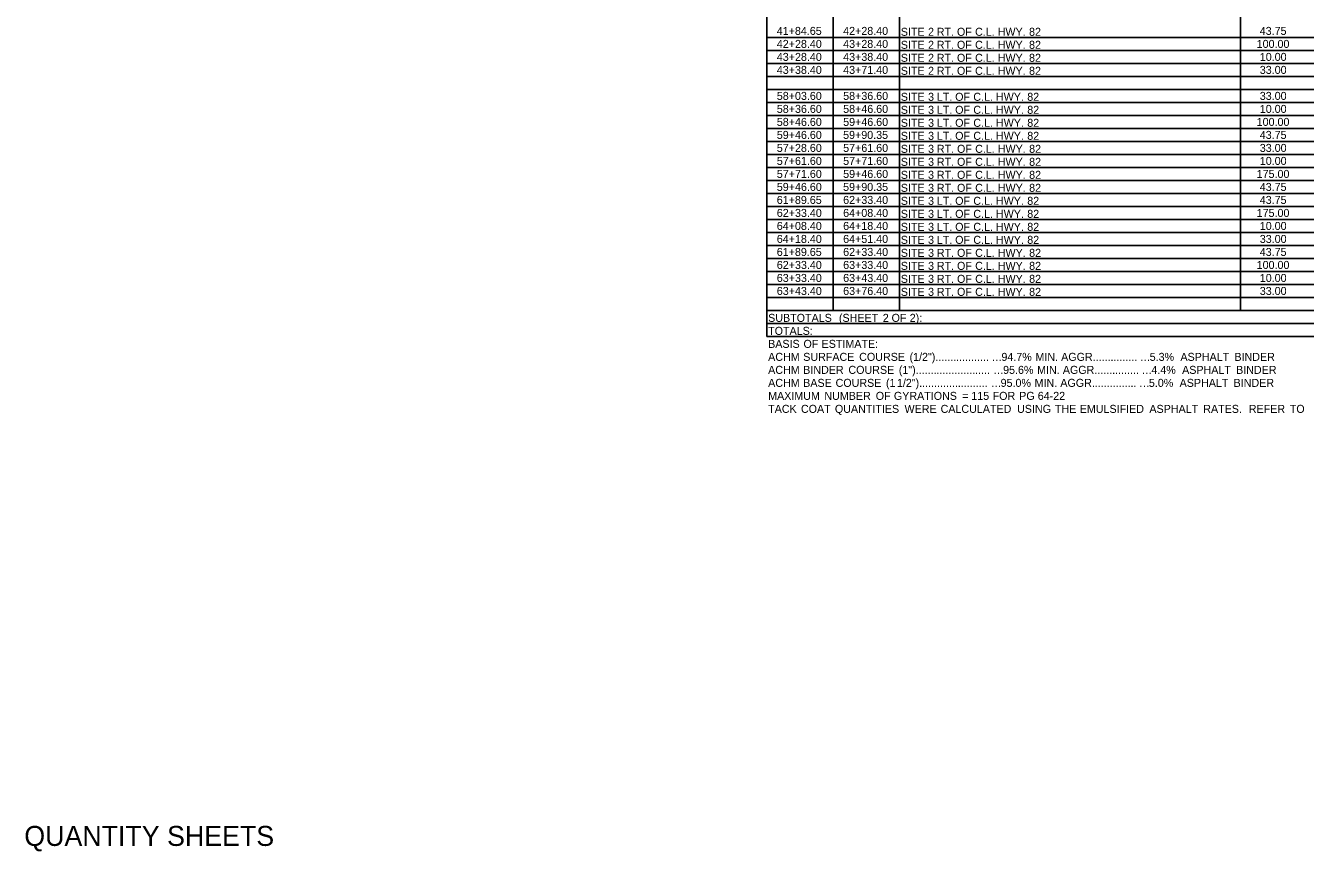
# Model space of a CAD drawing. Extents: x 977434 to 989596, y 1525697 to 1528336.
# Drawn here: x 984067 to 984835, y 1527332 to 1527827 of the extents above; entities that cross this region are included whole.
import ezdxf

# ---------------------------------------------------------------- set-up
doc = ezdxf.new("R2010")
doc.units = 0
doc.layers.add('Default', color=7, linetype='Continuous')
doc.layers.add('R_Border', color=7, linetype='Continuous')

msp = doc.modelspace()

# ---------------------------------------------------------------- linework, layer by layer
at = {"layer": 'Default'}
for p, q in [((984511.57, 1527640.86), (984511.57, 1528101.06)), ((984511.57, 1527640.86), (984511.57, 1528101.06)), ((984551.35, 1527656.46), (984551.35, 1528054.26)), ((984551.35, 1527656.46), (984551.35, 1528054.26)), ((984591.13, 1527656.46), (984591.13, 1528054.26)), ((984591.13, 1527656.46), (984591.13, 1528054.26)), ((984795.49, 1527656.46), (984795.49, 1528054.26)), ((984795.49, 1527656.46), (984795.49, 1528054.26)), ((984511.57, 1527820.26), (985869.55, 1527820.26)), ((984511.57, 1527812.46), (985869.55, 1527812.46)), ((984511.57, 1527804.66), (985869.55, 1527804.66)), ((984511.57, 1527796.86), (985869.55, 1527796.86)), ((984511.57, 1527789.06), (985869.55, 1527789.06)), ((984511.57, 1527781.26), (985869.55, 1527781.26)), ((984511.57, 1527773.46), (985869.55, 1527773.46)), ((984511.57, 1527765.66), (985869.55, 1527765.66)), ((984511.57, 1527757.86), (985869.55, 1527757.86)), ((984511.57, 1527750.06), (985869.55, 1527750.06)), ((984511.57, 1527742.26), (985869.55, 1527742.26)), ((984511.57, 1527734.46), (985869.55, 1527734.46)), ((984511.57, 1527726.66), (985869.55, 1527726.66)), ((984511.57, 1527718.86), (985869.55, 1527718.86)), ((984511.57, 1527711.06), (985869.55, 1527711.06)), ((984511.57, 1527703.26), (985869.55, 1527703.26)), ((984511.57, 1527695.46), (985869.55, 1527695.46)), ((984511.57, 1527687.66), (985869.55, 1527687.66)), ((984511.57, 1527679.86), (985869.55, 1527679.86)), ((984511.57, 1527672.06), (985869.55, 1527672.06)), ((984511.57, 1527664.26), (985869.55, 1527664.26)), ((984511.57, 1527656.46), (985869.55, 1527656.46)), ((984511.57, 1527648.66), (985869.55, 1527648.66)), ((984511.57, 1527640.86), (985869.55, 1527640.86))]:
    msp.add_line(p, q, dxfattribs=at)

# ---------------------------------------------------------------- texts
for s, p in [('41+84.65', (984517.52, 1527821.76)), ('42+28.40', (984557.33, 1527821.76)), ('SITE', (984591.91, 1527821.22)), (' 2', (984606.46, 1527821.22)), (' RT.', (984611.7, 1527821.22)), (' OF', (984623.78, 1527821.22)), (' C.L.', (984634.65, 1527821.22)), (' HWY.', (984648.22, 1527821.22)), (' 82', (984667.01, 1527821.22)), ('43.75', (984807.13, 1527821.76)), ('42+28.40', (984517.55, 1527813.96)), ('43+28.40', (984557.33, 1527813.96)), ('SITE', (984591.91, 1527813.42)), (' 2', (984606.46, 1527813.42)), (' RT.', (984611.7, 1527813.42)), (' OF', (984623.78, 1527813.42)), (' C.L.', (984634.65, 1527813.42)), (' HWY.', (984648.22, 1527813.42)), (' 82', (984667.01, 1527813.42)), ('100.00', (984805.29, 1527813.96)), ('43+28.40', (984517.55, 1527806.16)), ('43+38.40', (984557.33, 1527806.16)), ('SITE', (984591.91, 1527805.62)), (' 2', (984606.46, 1527805.62)), (' RT.', (984611.7, 1527805.62)), (' OF', (984623.78, 1527805.62)), (' C.L.', (984634.65, 1527805.62)), (' HWY.', (984648.22, 1527805.62)), (' 82', (984667.01, 1527805.62)), ('10.00', (984807.16, 1527806.16)), ('43+38.40', (984517.55, 1527798.36)), ('43+71.40', (984557.33, 1527798.36)), ('SITE', (984591.91, 1527797.82)), (' 2', (984606.46, 1527797.82)), (' RT.', (984611.7, 1527797.82)), (' OF', (984623.78, 1527797.82)), (' C.L.', (984634.65, 1527797.82)), (' HWY.', (984648.22, 1527797.82)), (' 82', (984667.01, 1527797.82)), ('33.00', (984807.16, 1527798.36)), ('58+03.60', (984517.55, 1527782.76)), ('58+36.60', (984557.33, 1527782.76)), ('SITE', (984591.91, 1527782.22)), (' 3', (984606.46, 1527782.22)), (' LT.', (984611.75, 1527782.22)), (' OF', (984622.71, 1527782.22)), (' C.L.', (984633.58, 1527782.22)), (' HWY.', (984647.16, 1527782.22)), (' 82', (984665.94, 1527782.22)), ('33.00', (984807.16, 1527782.76)), ('58+36.60', (984517.55, 1527774.96)), ('58+46.60', (984557.33, 1527774.96)), ('SITE', (984591.91, 1527774.42)), (' 3', (984606.46, 1527774.42)), (' LT.', (984611.75, 1527774.42)), (' OF', (984622.71, 1527774.42)), (' C.L.', (984633.58, 1527774.42)), (' HWY.', (984647.16, 1527774.42)), (' 82', (984665.94, 1527774.42)), ('10.00', (984807.16, 1527774.96)), ('58+46.60', (984517.55, 1527767.16)), ('59+46.60', (984557.33, 1527767.16)), ('SITE', (984591.91, 1527766.62)), (' 3', (984606.46, 1527766.62)), (' LT.', (984611.75, 1527766.62)), (' OF', (984622.71, 1527766.62)), (' C.L.', (984633.58, 1527766.62)), (' HWY.', (984647.16, 1527766.62)), (' 82', (984665.94, 1527766.62)), ('100.00', (984805.29, 1527767.16)), ('59+46.60', (984517.55, 1527759.36)), ('59+90.35', (984557.3, 1527759.36)), ('SITE', (984591.91, 1527758.82)), (' 3', (984606.46, 1527758.82)), (' LT.', (984611.75, 1527758.82)), (' OF', (984622.71, 1527758.82)), (' C.L.', (984633.58, 1527758.82)), (' HWY.', (984647.16, 1527758.82)), (' 82', (984665.94, 1527758.82)), ('43.75', (984807.13, 1527759.36)), ('57+28.60', (984517.55, 1527751.56)), ('57+61.60', (984557.33, 1527751.56)), ('SITE', (984591.91, 1527751.02)), (' 3', (984606.46, 1527751.02)), (' RT.', (984611.75, 1527751.02)), (' OF', (984623.83, 1527751.02)), (' C.L.', (984634.7, 1527751.02)), (' HWY.', (984648.27, 1527751.02)), (' 82', (984667.06, 1527751.02)), ('33.00', (984807.16, 1527751.56)), ('57+61.60', (984517.55, 1527743.76)), ('57+71.60', (984557.33, 1527743.76)), ('SITE', (984591.91, 1527743.22)), (' 3', (984606.46, 1527743.22)), (' RT.', (984611.75, 1527743.22)), (' OF', (984623.83, 1527743.22)), (' C.L.', (984634.7, 1527743.22)), (' HWY.', (984648.27, 1527743.22)), (' 82', (984667.06, 1527743.22)), ('10.00', (984807.16, 1527743.76)), ('57+71.60', (984517.55, 1527735.96)), ('59+46.60', (984557.33, 1527735.96)), ('SITE', (984591.91, 1527735.42)), (' 3', (984606.46, 1527735.42)), (' RT.', (984611.75, 1527735.42)), (' OF', (984623.83, 1527735.42)), (' C.L.', (984634.7, 1527735.42)), (' HWY.', (984648.27, 1527735.42)), (' 82', (984667.06, 1527735.42)), ('175.00', (984805.29, 1527735.96)), ('59+46.60', (984517.55, 1527728.16)), ('59+90.35', (984557.3, 1527728.16)), ('SITE', (984591.91, 1527727.62)), (' 3', (984606.46, 1527727.62)), (' RT.', (984611.75, 1527727.62)), (' OF', (984623.83, 1527727.62)), (' C.L.', (984634.7, 1527727.62)), (' HWY.', (984648.27, 1527727.62)), (' 82', (984667.06, 1527727.62)), ('43.75', (984807.13, 1527728.16)), ('61+89.65', (984517.52, 1527720.36)), ('62+33.40', (984557.33, 1527720.36)), ('SITE', (984591.91, 1527719.82)), (' 3', (984606.46, 1527719.82)), (' LT.', (984611.75, 1527719.82)), (' OF', (984622.71, 1527719.82)), (' C.L.', (984633.58, 1527719.82)), (' HWY.', (984647.16, 1527719.82)), (' 82', (984665.94, 1527719.82)), ('43.75', (984807.13, 1527720.36)), ('62+33.40', (984517.55, 1527712.56)), ('64+08.40', (984557.33, 1527712.56)), ('SITE', (984591.91, 1527712.02)), (' 3', (984606.46, 1527712.02)), (' LT.', (984611.75, 1527712.02)), (' OF', (984622.71, 1527712.02)), (' C.L.', (984633.58, 1527712.02)), (' HWY.', (984647.16, 1527712.02)), (' 82', (984665.94, 1527712.02)), ('175.00', (984805.29, 1527712.56)), ('64+08.40', (984517.55, 1527704.76)), ('64+18.40', (984557.33, 1527704.76)), ('SITE', (984591.91, 1527704.22)), (' 3', (984606.46, 1527704.22)), (' LT.', (984611.75, 1527704.22)), (' OF', (984622.71, 1527704.22)), (' C.L.', (984633.58, 1527704.22)), (' HWY.', (984647.16, 1527704.22)), (' 82', (984665.94, 1527704.22)), ('10.00', (984807.16, 1527704.76)), ('64+18.40', (984517.55, 1527696.96)), ('64+51.40', (984557.33, 1527696.96)), ('SITE', (984591.91, 1527696.42)), (' 3', (984606.46, 1527696.42)), (' LT.', (984611.75, 1527696.42)), (' OF', (984622.71, 1527696.42)), (' C.L.', (984633.58, 1527696.42)), (' HWY.', (984647.16, 1527696.42)), (' 82', (984665.94, 1527696.42)), ('33.00', (984807.16, 1527696.96)), ('61+89.65', (984517.52, 1527689.16)), ('62+33.40', (984557.33, 1527689.16)), ('SITE', (984591.91, 1527688.62)), (' 3', (984606.46, 1527688.62)), (' RT.', (984611.75, 1527688.62)), (' OF', (984623.83, 1527688.62)), (' C.L.', (984634.7, 1527688.62)), (' HWY.', (984648.27, 1527688.62)), (' 82', (984667.06, 1527688.62)), ('43.75', (984807.13, 1527689.16)), ('62+33.40', (984517.55, 1527681.36)), ('63+33.40', (984557.33, 1527681.36)), ('SITE', (984591.91, 1527680.82)), (' 3', (984606.46, 1527680.82)), (' RT.', (984611.75, 1527680.82)), (' OF', (984623.83, 1527680.82)), (' C.L.', (984634.7, 1527680.82)), (' HWY.', (984648.27, 1527680.82)), (' 82', (984667.06, 1527680.82)), ('100.00', (984805.29, 1527681.36)), ('63+33.40', (984517.55, 1527673.56)), ('63+43.40', (984557.33, 1527673.56)), ('SITE', (984591.91, 1527673.02)), (' 3', (984606.46, 1527673.02)), (' RT.', (984611.75, 1527673.02)), (' OF', (984623.83, 1527673.02)), (' C.L.', (984634.7, 1527673.02)), (' HWY.', (984648.27, 1527673.02)), (' 82', (984667.06, 1527673.02)), ('10.00', (984807.16, 1527673.56)), ('63+43.40', (984517.55, 1527665.76)), ('63+76.40', (984557.33, 1527665.76)), ('SITE', (984591.91, 1527665.22)), (' 3', (984606.46, 1527665.22)), (' RT.', (984611.75, 1527665.22)), (' OF', (984623.83, 1527665.22)), (' C.L.', (984634.7, 1527665.22)), (' HWY.', (984648.27, 1527665.22)), (' 82', (984667.06, 1527665.22)), ('33.00', (984807.16, 1527665.76)), ('SUBTOTALS', (984512.35, 1527649.62)), (' (SHEET', (984553.01, 1527649.62)), (' 2', (984579.33, 1527649.62)), (' OF', (984584.59, 1527649.62)), (' 2):', (984595.45, 1527649.62)), ('TOTALS:', (984512.35, 1527641.82)), ('BASIS', (984512.35, 1527634.02)), (' OF', (984531.76, 1527634.02)), (' ESTIMATE:', (984542.63, 1527634.02)), ('ACHM', (984512.35, 1527626.22)), (' SURFACE', (984531.6, 1527626.22)), (' COURSE', (984565.15, 1527626.22)), (' (1/2")..................', (984595.35, 1527626.22)), ('94.7%', (984652.23, 1527626.22)), (' MIN.', (984670.83, 1527626.22)), (' AGGR...............', (984686.26, 1527626.22)), ('5.3%', (984741.14, 1527626.22)), ('  ASPHALT', (984756, 1527626.22)), (' BINDER', (984790.16, 1527626.22)), ('ACHM', (984512.35, 1527618.42)), (' BINDER', (984531.6, 1527618.42)), (' COURSE', (984558.71, 1527618.42)), (' (1").........................', (984588.91, 1527618.42)), ('…', (984646.31, 1527626.22)), ('95.6%', (984653.24, 1527618.42)), (' MIN.', (984671.83, 1527618.42)), (' AGGR...............', (984687.26, 1527618.42)), ('…', (984735.22, 1527626.22)), ('4.4%', (984742.14, 1527618.42)), ('  ASPHALT', (984757.01, 1527618.42)), (' BINDER', (984791.16, 1527618.42)), ('ACHM', (984512.35, 1527610.62)), (' BASE', (984531.6, 1527610.62)), (' COURSE', (984551, 1527610.62)), (' (1', (984581.2, 1527610.62)), (' 1/2").......................', (984587.79, 1527610.62)), ('…', (984647.32, 1527618.42)), ('95.0%', (984651.75, 1527610.62)), (' MIN.', (984670.34, 1527610.62)), (' AGGR...............', (984685.77, 1527610.62)), ('…', (984736.22, 1527618.42)), ('5.0%', (984740.65, 1527610.62)), ('  ASPHALT', (984755.52, 1527610.62)), (' BINDER', (984789.67, 1527610.62)), ('MAXIMUM', (984512.35, 1527602.82)), (' NUMBER', (984544.26, 1527602.82)), (' OF', (984575.1, 1527602.82)), (' GYRATIONS', (984585.97, 1527602.82)), (' 115', (984632.39, 1527602.82)), ('…', (984645.83, 1527610.62)), (' FOR', (984645.17, 1527602.82)), (' PG', (984661.1, 1527602.82)), (' 64-22', (984672.23, 1527602.82)), ('…', (984734.73, 1527610.62)), ('TACK', (984512.35, 1527595.02)), (' COAT', (984530.23, 1527595.02)), (' QUANTITIES', (984550.59, 1527595.02)), (' CALCULATED', (984613.97, 1527595.02)), (' =', (984626.99, 1527602.82)), (' USING', (984659.83, 1527595.02)), (' EMULSIFIED', (984697.43, 1527595.02)), (' ASPHALT', (984739.18, 1527595.02)), (' RATES.', (984771.48, 1527595.02)), (' TO', (984823.35, 1527595.02)), (' WERE', (984592.35, 1527595.02)), (' THE', (984682.51, 1527595.02)), ('  REFER', (984796.98, 1527595.02))]:
    msp.add_text(s, height=4.8, dxfattribs=at).set_placement(p)
at = {"layer": 'R_Border'}
msp.add_text('QUANTITY SHEETS', height=12, rotation=360, dxfattribs=at).set_placement((984066.33, 1527335.24))

doc.saveas('drawing.dxf')
